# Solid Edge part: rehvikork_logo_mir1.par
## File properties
Author: KULL
Template: Iso Metric Part.par
Last saved by: KULL
Revision: 2
Application: Solid Edge
Accuracy: 0,990
Username: KULL
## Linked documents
rehvikork_logo.par
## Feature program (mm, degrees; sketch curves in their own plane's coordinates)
part copy "CopiedPart_1"
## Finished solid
Body 1: solid body, 86 faces, 199 edges, 116 vertices, 2 separate solids.
  Faces by surface: spline 40, blend 36, sphere 8, cone 1, torus 1
  Edges by curve: intersection 112, line 32, circle 29, curve on surface 26
Bounding box of the edges (mm; curved faces can reach further): 1.405 x 13.917 x 13.917, from (-0.4589, -6.9587, -6.9587) to (0.946, 6.9587, 6.9587).
Conical faces (half-angle, radius in mm at the cone's reference point): 11.8765 deg R7 x1
Toroidal faces (ring radius, tube radius in mm): R6.763 r0.2 x1
Spherical faces by radius (mm): R0.2 x4, R33.3132 x2, R34.0132 x2
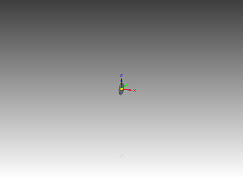
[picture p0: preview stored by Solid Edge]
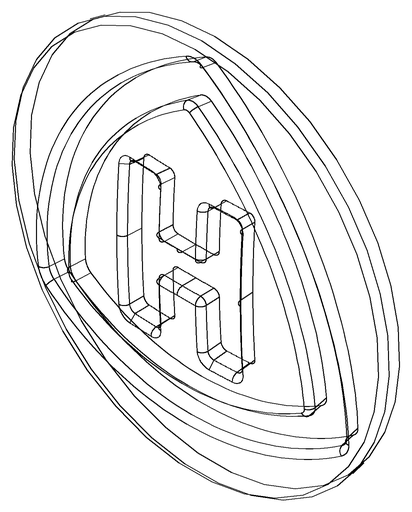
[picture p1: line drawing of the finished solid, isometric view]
